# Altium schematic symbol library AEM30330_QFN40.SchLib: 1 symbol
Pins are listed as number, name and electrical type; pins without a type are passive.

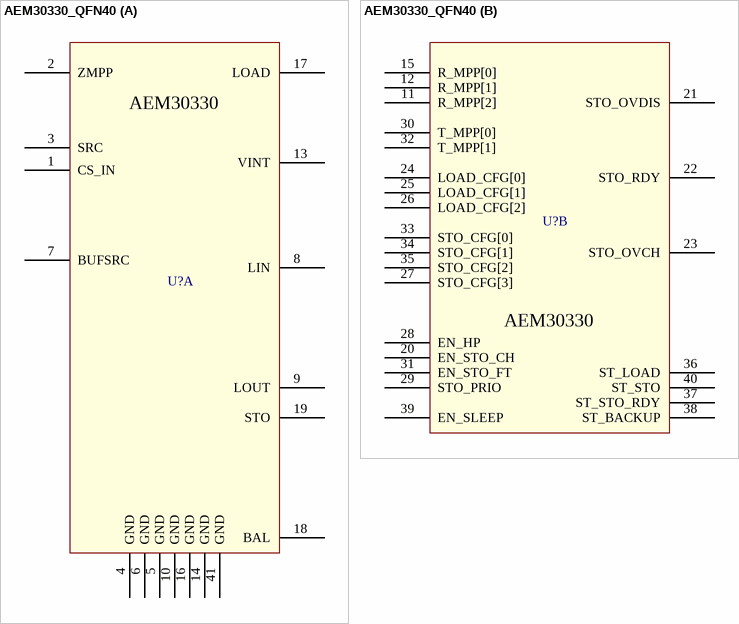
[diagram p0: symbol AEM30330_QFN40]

## AEM30330_QFN40
designator U?  (value not drawn)
footprint QFN40P500X500X90_HS-41N - pad 0.25x0.85mm via 0.3mm (QFN, 40-Leads, Body 5.00x5.00mm, Pitch 0.40mm, Thermal Pad 3.30x3.30mm, IPC Medium Density)
part A pins: 1 CS_IN, 2 ZMPP, 3 SRC, 4 GND, 5 GND, 6 GND, 7 BUFSRC, 8 LIN, 9 LOUT, 10 GND, 13 VINT, 14 GND, 16 GND, 17 LOAD, 18 BAL, 19 STO, 41 GND
part B pins: 11 R_MPP[2], 12 R_MPP[1], 15 R_MPP[0], 20 EN_STO_CH, 21 STO_OVDIS, 22 STO_RDY, 23 STO_OVCH, 24 LOAD_CFG[0], 25 LOAD_CFG[1], 26 LOAD_CFG[2], 27 STO_CFG[3], 28 EN_HP, 29 STO_PRIO, 30 T_MPP[0], 31 EN_STO_FT, 32 T_MPP[1], 33 STO_CFG[0], 34 STO_CFG[1], 35 STO_CFG[2], 36 ST_LOAD, 37 ST_STO_RDY, 38 ST_BACKUP, 39 EN_SLEEP, 40 ST_STO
